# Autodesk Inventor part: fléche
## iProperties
Shininess: 64.0
Length Units: 11269
Angle Units: 11279
Time Units: 11290
Mass Units: 11283
Length Display Precision: 3
Angle Display Precision: 2
Compacted: True
Part Number: fléche
Document SubType Name: Modeling
Created: 2003-10
Material: Par défaut
Designer: Maison
Density: 0.0
Volumn: 0.0
Area: 0.0
PropertySet Name: Model Information
Control State: 0
Master: False
Checked Out: False
Author: Maison
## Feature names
1. Extrusion1
